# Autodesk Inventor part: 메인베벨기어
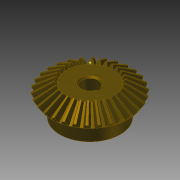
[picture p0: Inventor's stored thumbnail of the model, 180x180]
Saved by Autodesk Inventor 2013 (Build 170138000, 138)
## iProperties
Created: 2018-09
Part Number: 메인베벨기어
Material: 강철, 탄소
Document SubType Name: Modeling
Categories: <?xml version="1.0" encoding="UTF-16"?> <MemberInstance><Categories><FamilyTemplate><FamilyTemplateParameter ValueType="xs:double" Id="1" ObjectReferenceKey="da
Mass: 290.333 g
Surface Area: 107.709 cm^2
Volume: 36.8911 cm^3
Density: 7.87 g/cm^3
CustomPartVersion: 1
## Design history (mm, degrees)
node "맨 위 점"
node "메쉬 평면2"
sketch "톱니 본체 스케치"
  geometry: L1 (0, 0)-(28.669, -21.997); L2 (28.669, -21.997)-(31.109, -18.336); L3 (31.109, -18.336)-(0, 0); L4 (30, -20)-(0, 0); L5 (17.219, -13.212)-(18.685, -11.013); L6 (28.669, -21.997)-(17.219, -13.212); L7 (31.109, -18.336)-(18.685, -11.013); L8 (0, -39.387)-(0, 6.564) reference; L9 (0, -20)-(31.109, -20)
  constraints: 16 end point, 4 point on line, 3 perpendicular, 2 collinear, 1 horizontal alignment, 1 vertical alignment
  dimensions: "d0" = 60 diameter of L4.start L8 (= da_de); "d1" = 57.33744 diameter of L1.end L8 (= da_dfe); "d2" = 62.2188 diameter of L2.end L8 (= da_dae); "d3" = 14.4 distance between parallel lines of L2 L5 (= da_b); "d4" = 18.3359 vertical distance of L2.end L1.start (= da_ve)
revolve "톱니 본체" sketch "톱니 본체 스케치" stored, may be unused: angle "d5" = 90 deg
node "시작점"
node "톱니 평면"
sketch "시작 스케치"
  geometry: L1 (0, -23.505)-(0, 10.645) reference; L2 (-0.709, -2.928)-(0.709, -2.928); A1 r 19.188 centre (-19.457, -7.014) between (-0.709, -2.928) and (-3.232, 3.229); A2 r 19.188 centre (19.457, -7.014) between (3.232, 3.229) and (0.709, -2.928); A3 r 57.403 centre (0, -54.083) between (3.232, 3.229) and (-3.232, 3.229); 1 further point
  constraints: 6 point on circle, 3 centre point, 3 symmetric about line, 2 end point, 1 coincident, 1 perpendicular, 1 other
  dimensions: "d7" = 19.18795 radius of A1 (= fd_rr); "d8" = 19.45712 horizontal distance of point (0, -54.083) A1.centre (= fd_x); "d9" = 47.06905 vertical distance of point (0, -54.083) A1.centre (= fd_y); "d57" = 57.40327 radius of A3 (= 0.5 x fd_dva + 0.3 x da_he); "d58" = 51.15527 distance from line of A3.centre L2 (= 0.5 x fd_dva - 1.12 x da_he)
node "끝점"
  node "끝 평면"
sketch "3D 스케치 오른쪽"
  node "Helical Curve Right" dims "d65" = 229.90621 (computed from da_dm, da_delta, da_beta), "d66" = 31.5, "d67" = 60 (= da_de), "d68" = -9.82794 (= -da_delta), "d69" = 8.10972 (computed from fd_loft, da_delta)
node "끝 평면 오른쪽"
sketch "끝 스케치 오른쪽"
  geometry: L1 (0, -41.54)-(0, 13.178) reference; L2 (-0.422, -1.69)-(0.422, -1.69); A1 r 11.427 centre (-11.587, -4.123) between (-0.422, -1.69) and (-1.925, 1.977); A2 r 11.427 centre (11.587, -4.123) between (1.925, 1.977) and (0.422, -1.69); A3 r 34.184 centre (0, -32.153) between (1.925, 1.977) and (-1.925, 1.977); 1 further point
  constraints: 6 point on circle, 3 centre point, 3 symmetric about line, 2 end point, 1 coincident, 1 perpendicular, 1 other
  dimensions: "d70" = 11.58699 horizontal distance of A3.centre A1.centre (computed from fd_x, fd_ratio); "d71" = 28.03028 vertical distance of point (0, -32.153) A1.centre (computed from fd_y, fd_ratio); "d72" = 11.4267 radius of A1 (computed from fd_rr, fd_ratio); "d73" = 30.46369 distance from line of point (0, -32.153) L2 (computed from d58, fd_ratio); "d74" = 34.18446 radius of A3 (computed from d57, fd_ratio)
feature "로프트 오른쪽" sketch "끝 스케치 오른쪽" dims "d75" = 0, "d77" = 0, "d79" = 0, "d80" = 90 deg, "d85" = 20, "d92" = 90 deg, "d93" = 90 deg, "da_teethtype" = 0 [user parameter]
sketch "3D 스케치 왼쪽"
  node "Helical Curve Left" dims "d26" = 229.90621 (computed from da_dm, da_delta, da_beta), "d27" = 8.10972 (computed from fd_loft, da_delta), "d28" = 60 (= da_de), "d29" = -9.82794 (= -da_delta)
node "끝 평면 왼쪽"
sketch "끝 스케치 왼쪽" dims "d56" = 10.3728 (derived)
  geometry: L1 (0, -43.753)-(0, 15.405) reference; L2 (-0.422, -1.678)-(0.422, -1.678); A1 r 11.427 centre (-11.587, -4.111) between (-0.422, -1.678) and (-1.925, 1.988); A2 r 11.427 centre (11.587, -4.111) between (1.925, 1.988) and (0.422, -1.678); A3 r 34.184 centre (0, -32.142) between (1.925, 1.988) and (-1.925, 1.988); 2 further points; 1 other entity
  constraints: 6 point on circle, 3 centre point, 3 symmetric about line, 2 end point, 1 coincident, 2 other
  dimensions: "d30" = 11.4267 radius of A1 (computed from fd_rr, fd_ratio); "d31" = 11.58699 horizontal distance of point (0, -32.142) A1.centre (computed from fd_x, fd_ratio); "d32" = 28.03028 vertical distance of A1.centre point (0, -32.142) (computed from fd_y, fd_ratio); "d61" = 34.18446 radius of A3 (computed from d57, fd_ratio); "d62" = 30.46369 distance from line of point (0, -32.142) L2 (computed from d58, fd_ratio)
feature "로프트 왼쪽" sketch "끝 스케치 왼쪽" dims "d35" = 0, "d37" = 0, "d39" = 0, "d40" = 90 deg, "d84" = 10, "d90" = 90 deg, "d91" = 90 deg, "da_teethtype" = 0 [user parameter]
sketch "본체 스케치"
  geometry: L1 (0, -35.038)-(0, -19.531) reference; L2 (28.669, -21.997)-(17.219, -13.212) reference; L3 (17.219, -13.212)-(0, -13.212); L4 (28.669, -21.997)-(0, -21.997)
  constraints: 4 end point, 2 perpendicular, 2 point on line
revolve "본체 고정" sketch "본체 스케치" stored, may be unused: angle "d46" = 90 deg
feature "피치 지름" dims angle "d47" = 90 deg
sketch "스케치8"
  geometry: C1 r 22.5 at (0, 0); 1 further point
  constraints: 1 centre point, 1 coincident
  dimensions: "d94" = 45 diameter of C1
extrude "돌출1" join sketch "스케치8" distance "d95" = 13; taper "d96" = 0 deg
sketch "스케치9"
  geometry: 1 further point
hole "구멍1" sketch "스케치9" at (0, 0) diameter "d97" = 12; stored, may be unused: countersink angle "d101" = 90 deg, drill point angle "d103" = 118 deg; dims "d98" = 6, "d99" = 4, "d100" = 2, "d102" = 8
sketch "스케치10"
  geometry: L1 (5.657, 2)-(7.8, 2); L2 (7.8, 2)-(7.8, -2); L3 (7.8, -2)-(5.657, -2); A1 r 6 centre (0, 0) between (5.657, 2) and (5.657, -2) reference; 1 further point
  constraints: 6 end point, 2 parallel, 2 point on circle, 1 horizontal, 1 perpendicular
  dimensions: "d104" = 4 distance of L1.end L2.end; "d112" = 13.8 dimension on A1 L2
extrude "돌출2" cut sketch "스케치10" stored distance "d106" = 10; taper "d107" = 0 deg
chamfer "모따기1" distance "d108" = 1; stored, may be unused: second distance "d109" = 2, angle "d110" = 45 deg
fillet "모깎기1" dims "d111" = 2
body "Solid1"
feature "로프트" dims "d17" = 0, "d18" = 90 deg, "d19" = 0, "d20" = 90 deg, "d89" = 0, "da_teethtype" = 0 [user parameter]
pattern_circular "원형 패턴" dims angle "d22" = 360 deg, "d88" = 0, "da_teethtype" = 0 [user parameter]
pattern_circular "원형 패턴 오른쪽" dims angle "d82" = 360 deg, "da_teethtype" = 0 [user parameter]
pattern_circular "원형 패턴 왼쪽" dims angle "d42" = 360 deg, "da_teethtype" = 0 [user parameter]
sketch "끝 스케치"
  geometry: L1 (0, -15.359)-(0, 6.983) reference; L2 (-0.422, -1.69)-(0.422, -1.69); A1 r 11.427 centre (-11.587, -4.123) between (-0.422, -1.69) and (-1.925, 1.977); A2 r 11.427 centre (11.587, -4.123) between (1.925, 1.977) and (0.422, -1.69); A3 r 34.184 centre (0, -32.153) between (1.925, 1.977) and (-1.925, 1.977); 1 further point
  constraints: 6 point on circle, 3 centre point, 3 symmetric about line, 2 end point, 1 coincident, 1 other
  dimensions: "d12" = 11.4267 radius of A1 (computed from fd_rr, fd_ratio); "d15" = 11.58699 horizontal distance of A1.centre point (0, -32.153) (computed from fd_x, fd_ratio); "d16" = 28.03028 vertical distance of A1.centre point (0, -32.153) (computed from fd_y, fd_ratio); "d59" = 34.18446 radius of A3 (computed from d57, fd_ratio); "d60" = 30.46369 distance from line of A3.centre L2 (computed from d58, fd_ratio)
sketch "Sketch6"
  geometry: L1 (30, -20)-(0, 0) reference; L2 (0, -37.8)-(0, 6.3) reference
body "Srf1"
other parameters: "da_b" = 14.4 [user parameter; used in 2 equation terms], "da_de" = 60 [user parameter; used in 4 equation terms], "da_dae" = 62.2188 [user parameter; used in 2 equation terms], "da_dfe" = 57.33744 [user parameter; used in 1 equation term], "da_le" = 36.05551 [user parameter; used in 1 equation term], "da_omega" = 90 deg [user parameter; used in 1 equation term], "da_beta" = 0 [user parameter; used in 2 equation terms], "da_delta" = 9.82794 [user parameter; used in 8 equation terms], "da_alpha" = 20 deg [user parameter; used in 2 equation terms], "da_he" = 4.4 [user parameter; used in 4 equation terms], "da_ve" = 18.3359 [user parameter; used in 1 equation term], "fd_dv" = 108.16654 (computed from da_de, da_delta) [user parameter; used in 1 equation term], "fd_dva" = 112.16654 (computed from da_dae, da_delta) [user parameter; used in 3 equation terms], "fd_dvb" = 101.6433 (computed from fd_dv, da_alpha) [user parameter; used in 2 equation terms], "da_zv" = 540.83269 [user parameter; used in 1 equation term], "fd_loft" = 14.62 (= da_b + 0.05 x da_he) [user parameter; used in 4 equation terms], "fd_ratio" = 5.95514 (computed from da_le, fd_loft) [user parameter; used in 15 equation terms], "fd_rr" = 19.18795 (computed from fd_dd, fd_dvb) [user parameter; used in 6 equation terms], "fd_angle" = 0.29367 (computed from da_zv) [user parameter; used in 4 equation terms], "fd_x1" = 1.58802 (computed from da_dvw, fd_angle) [user parameter; used in 1 equation term], "fd_y1" = 54.05995 (computed from da_dvw, fd_angle) [user parameter; used in 1 equation term], "fd_x2" = 17.8691 (computed from fd_rr, fd_angle2, fd_angle) [user parameter; used in 1 equation term], "fd_y2" = 6.9909 (computed from fd_rr, fd_angle2, fd_angle) [user parameter; used in 1 equation term], "fd_x" = 19.45712 (= fd_x1 + fd_x2) [user parameter; used in 4 equation terms], "fd_y" = 47.06905 (= fd_y1 - fd_y2) [user parameter; used in 4 equation terms], "fd_angle2" = 3.43555 (computed from fd_dvb, fd_dd, da_alpha) [user parameter; used in 2 equation terms], "fd_dd" = 108.64654 (= fd_dva - 0.8 x da_he) [user parameter; used in 2 equation terms], "da_dvw" = 108.16654 [user parameter; used in 2 equation terms], "d11" = 14.62 (= fd_loft), "da_dm" = 48.01848 [user parameter; used in 2 equation terms], "da_x" = 0 [user parameter], "da_m" = 2 [user parameter], "d48" = 0, "d49" = 0, "d50" = 90 deg (= da_omega), "d51" = 6 deg (computed from da_z), "d52" = 0, "d53" = 0, "d54" = 0
